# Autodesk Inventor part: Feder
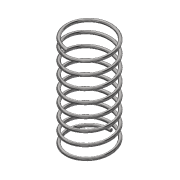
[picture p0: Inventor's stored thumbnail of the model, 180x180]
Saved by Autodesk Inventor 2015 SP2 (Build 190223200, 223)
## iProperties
Created: 2017-07
Material: Federstahl
Document SubType Name: Modeling
Designer: UR
Density: 7.85 g/cm^3
Appearance: Stahl - poliert
Description: Dr Ø1x155
Part Number: Feder
Mass: 0.372761 g
Surface Area: 3.80673 cm^2
Volume: 0.0474855 cm^3
Author: UR
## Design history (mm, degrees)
sketch "Skizze1"
  geometry: L1 (0, 0)-(0, 1.626); C1 r 0.25 at (3.5, 0)
  constraints: 2 end point, 1 centre point, 1 horizontal alignment, 1 vertical
  dimensions: "d8" = 0.5 diameter of C1; "d9" = 7 diameter of C1.centre L1
feature "Spirale1" sketch "Skizze1" pitch "d0" = 2; turns "d2" = 7; dims "d1" = 14.6, "d3" = 0, angle "d4" = 179.99 deg, angle "d5" = 90 deg, "d6" = 31.41418, "d7" = 90 deg
node "Mittelachse"
node "Volumenkörper1"
